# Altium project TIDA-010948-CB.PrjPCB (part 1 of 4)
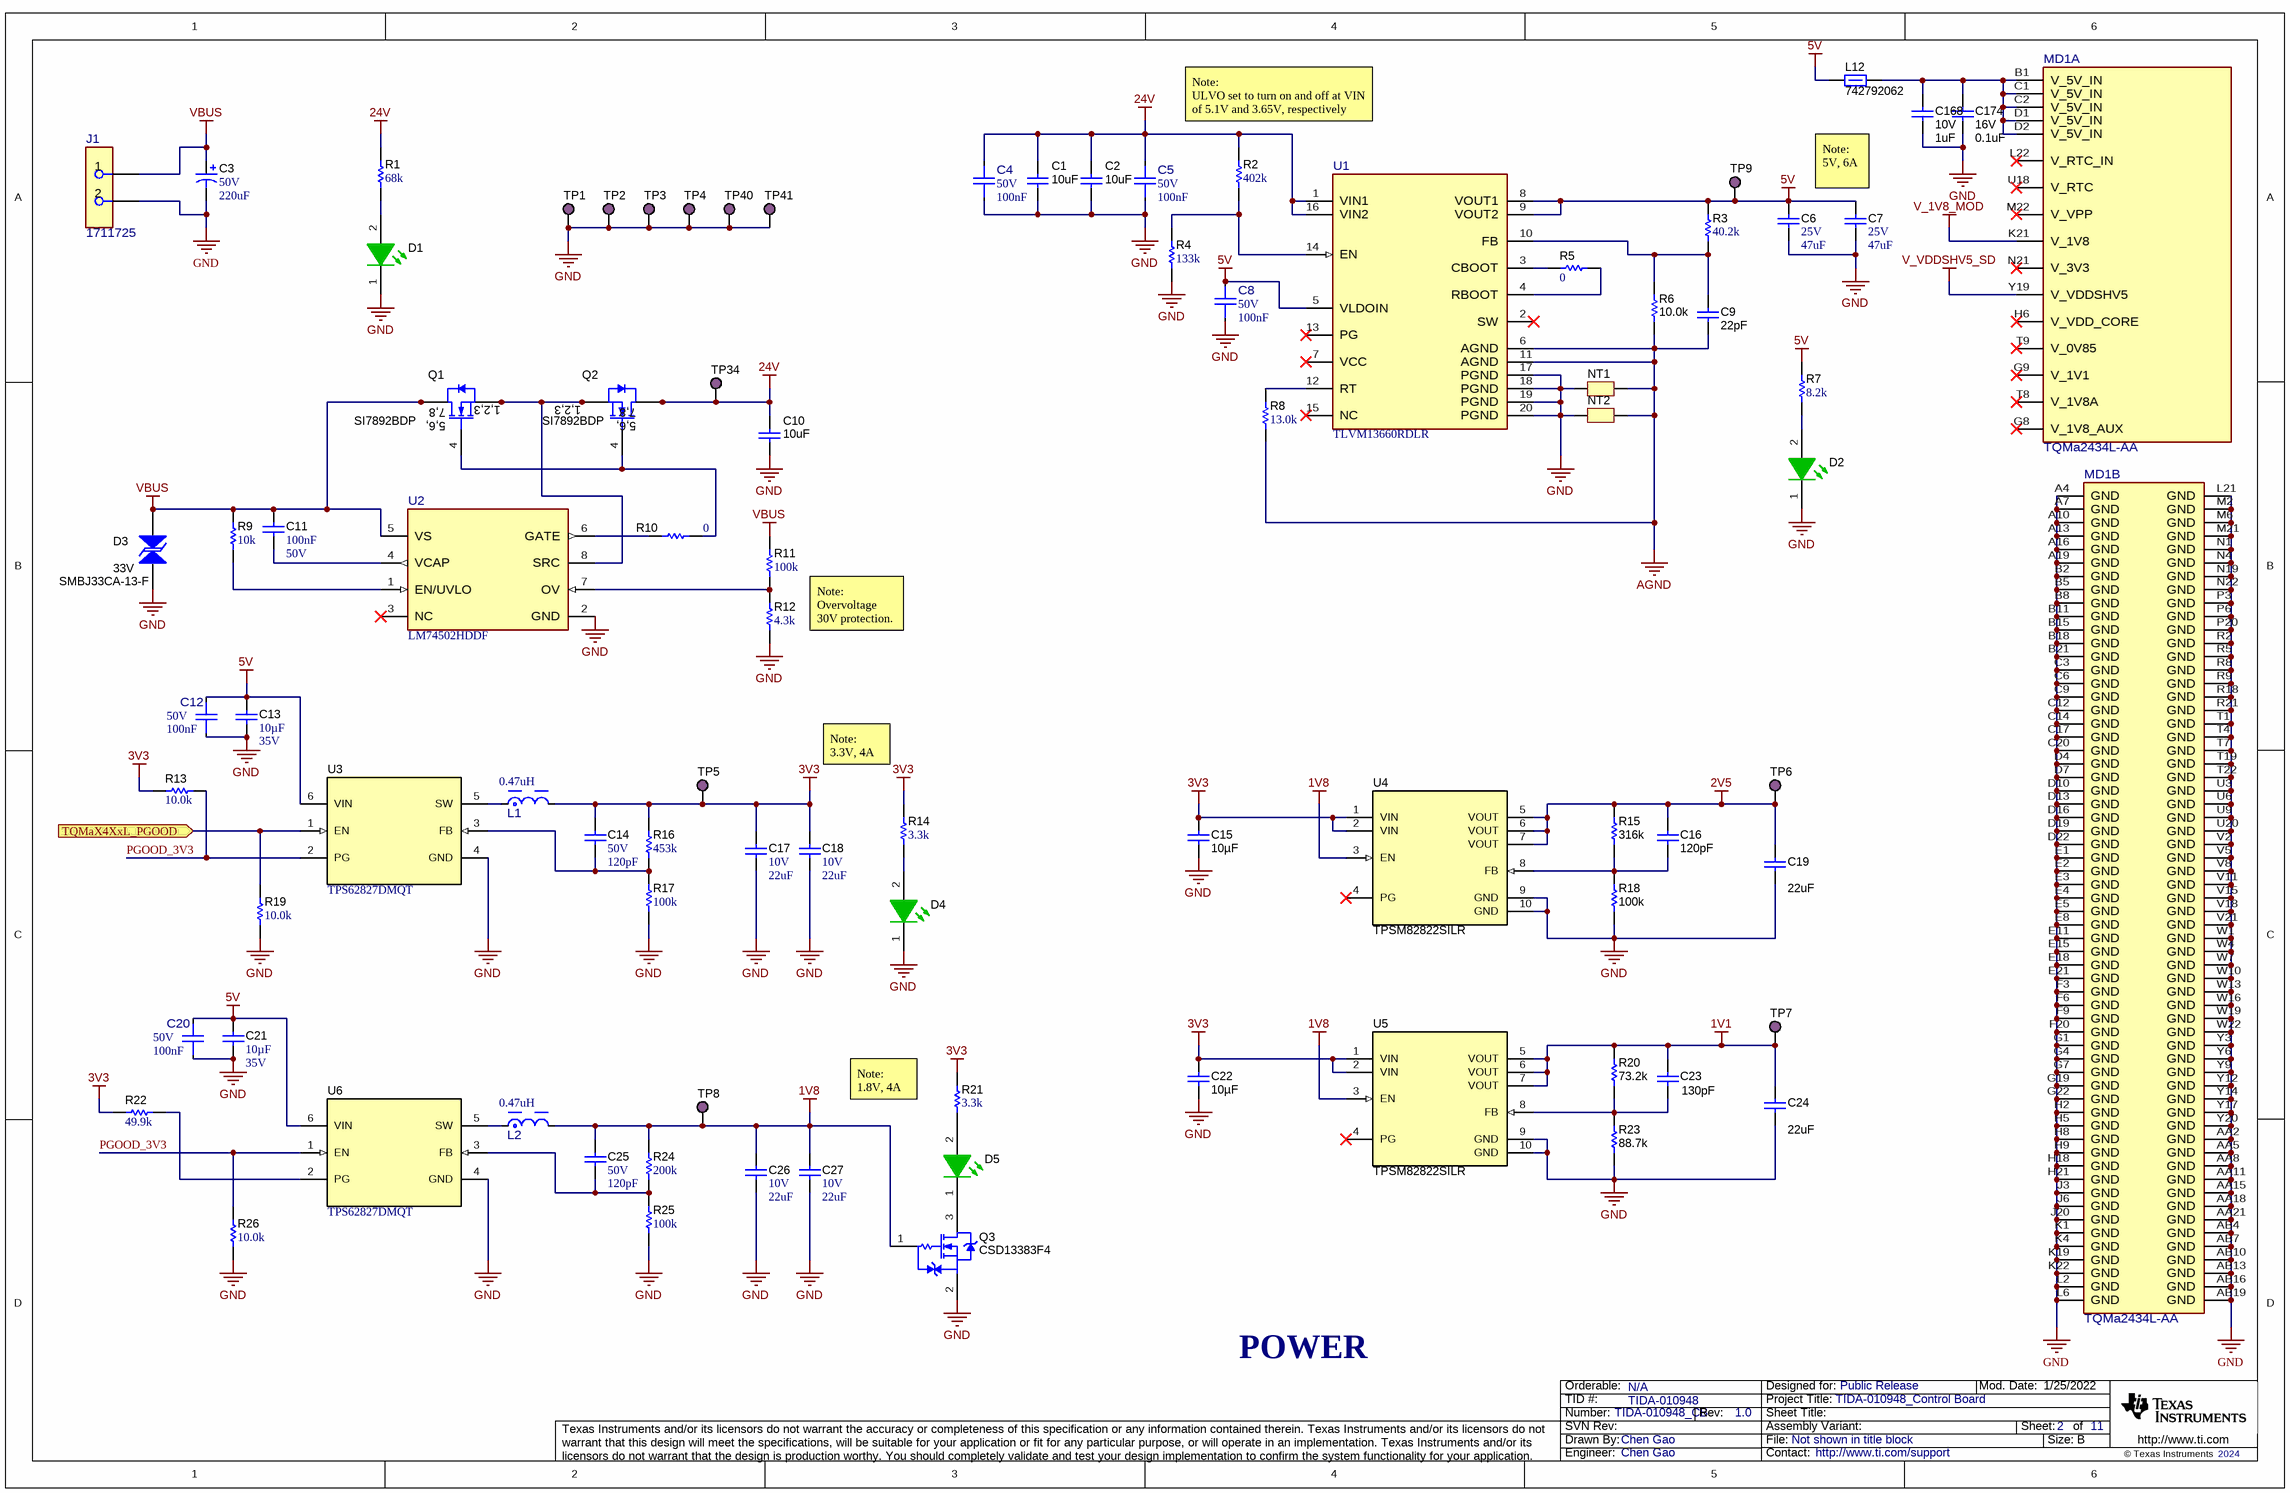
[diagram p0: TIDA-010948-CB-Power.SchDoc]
TID: TIDA-010948; TechSupport: http://www.ti.com/support; SCH_Rev: 1.0; PRJ_Title: TIDA-010948_Control Board; PRJ_Number: TIDA-010948_CB; PRJ_Engineer: Chen Gao; PRJ_Customer: Public Release; PCB_Rev: 1.0; PCB_Layout: TIDA-010948_CB; DrawnBy: Chen Gao; EVM_orderable: N/A; CopyrightYear: 2024
11 sheets, 712 parts. Net scope: flat (ports and power ports of the same name join across sheets).
Board file: TIDA-010948-CB.PcbDoc
Sheets:
  TIDA-010948-CB-BlockDiagram.SchDoc
  TIDA-010948-CB-Power.SchDoc
  TIDA-010948-CB-Bootmode.SchDoc
  TIDA-010948-CB-Debug.SchDoc
  TIDA-010948-CB-SDFM.SchDoc
  TIDA-010948-CB-PRUIO_CLKGEN.SchDoc
  TIDA-010948-CB-PWM.SchDoc
  TIDA-010948-CB-Ethernet1.SchDoc
  TIDA-010948-CB-Ethernet2.SchDoc
  TIDA-010948-CB-Interface.SchDoc
  TIDA-010948-CB-Hardware.SchDoc

## Sheet TIDA-010948-CB-BlockDiagram.SchDoc
size 431 x 279 mm; Date: Not shown in title block; ApprovedBy: Not shown in title block; CheckedBy: Not shown in title block; Author: Not shown in title block; CompanyName: Not shown in title block; Engineer: Not shown in title block; Organization: Not shown in title block; Address1: Not shown in title block; Address2: Not shown in title block; Address3: Not shown in title block; Address4: Not shown in title block; DocumentNumber: 11; Revision: Use project parameter SCH_Rev; SheetNumber: 1; SheetTotal: 11; PageSetup: Record=PageOptions¦CenterHorizontal=True¦CenterVertical=True¦PrintScale=1.00¦XCorrection=1.00¦YCorrection=1.00¦PrintKind=0¦BorderSize=5000000¦LeftOffset=0¦BottomOffset=0¦Orientation=2¦PaperLength=1000¦PaperWidth=1000¦Scale=100¦PaperSource=15¦PrintQuality=600¦MediaType=1¦DitherType=10¦PaperKind=Letter¦PrintScaleMode=1

## Sheet TIDA-010948-CB-Power.SchDoc
size 431 x 279 mm; Date: Not shown in title block; ApprovedBy: Not shown in title block; CheckedBy: Not shown in title block; Author: Not shown in title block; CompanyName: Not shown in title block; Engineer: Not shown in title block; Organization: Not shown in title block; Address1: Not shown in title block; Address2: Not shown in title block; Address3: Not shown in title block; Address4: Not shown in title block; DocumentNumber: 2; Revision: Use project parameter SCH_Rev; SheetNumber: 2; SheetTotal: 11; PageSetup: Record=PageOptions¦CenterHorizontal=True¦CenterVertical=True¦PrintScale=1.00¦XCorrection=1.00¦YCorrection=1.00¦PrintKind=0¦BorderSize=5000000¦LeftOffset=0¦BottomOffset=0¦Orientation=2¦PaperLength=1000¦PaperWidth=1000¦Scale=100¦PaperSource=15¦PrintQuality=600¦MediaType=1¦DitherType=10¦PaperKind=Letter¦PrintScaleMode=1

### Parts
C1  ValueDisplayed: 10uF  [1210_270L]  (hidden comment: GRM32ER71H106KA12L)
C2  ValueDisplayed: 10uF  [1210_270L]  (hidden comment: GRM32ER71H106KA12L)
C3  VDC_V: 50V  ValueDisplayed: 220uF  [SM_RADIAL_G]  (hidden comment: EEE-FK1H221P)
C4  VDC_V: 50V  ValueDisplayed: 100nF  [FP-885012205086_0402-MFG]  (hidden comment: 885012205086)
C5  VDC_V: 50V  ValueDisplayed: 100nF  [FP-885012205086_0402-MFG]  (hidden comment: 885012205086)
C6  VDC_V: 25V  ValueDisplayed: 47uF  [1206_190]  (hidden comment: C3216X5R1E476M160AC)
C7  VDC_V: 25V  ValueDisplayed: 47uF  [1206_190]  (hidden comment: C3216X5R1E476M160AC)
C8  VDC_V: 50V  ValueDisplayed: 100nF  [FP-885012205086_0402-MFG]  (hidden comment: 885012205086)
C9  ValueDisplayed: 22pF  [0402L]  (hidden comment: CGA2B2NP01H220J050BA)
C10  ValueDisplayed: 10uF  [1210_270L]  (hidden comment: GRM32ER71H106KA12L)
C11  Cap_F: 100nF  VDC_V: 50V  [0603]  (hidden comment: GCM188R71H104KA57D)
C12  VDC_V: 50V  ValueDisplayed: 100nF  [FP-885012205086_0402-MFG]  (hidden comment: 885012205086)
C13  ValueDisplayed: 10µF  VDC_V: 35V  [0805_HV1]  (hidden comment: C2012JB1V106K125AC)
C14  VDC_V: 50V  ValueDisplayed: 120pF  [0402L]  (hidden comment: GRM1555C1H121JA01D)
C15  Cap_F: 10µF  [0603]  (hidden comment: GRM188Z71A106MA73D)
C16  ValueDisplayed: 120pF  [0603]  (hidden comment: GRM1885C1H121JA01D)
C17  VDC_V: 10V  ValueDisplayed: 22uF  [0603L]  (hidden comment: GRM187R61A226ME15D)
C18  VDC_V: 10V  ValueDisplayed: 22uF  [0603L]  (hidden comment: GRM187R61A226ME15D)
C19  ValueDisplayed: 22uF  [0805_HV]  (hidden comment: GRM21BR61E226ME44L)
C20  VDC_V: 50V  ValueDisplayed: 100nF  [FP-885012205086_0402-MFG]  (hidden comment: 885012205086)
C21  ValueDisplayed: 10µF  VDC_V: 35V  [0805_HV1]  (hidden comment: C2012JB1V106K125AC)
C22  Cap_F: 10µF  [0603]  (hidden comment: GRM188Z71A106MA73D)
C23  ValueDisplayed: 130pF  [0603]  (hidden comment: GRM1885C1H131JA01D)
C24  ValueDisplayed: 22uF  [0805_HV]  (hidden comment: GRM21BR61E226ME44L)
C25  VDC_V: 50V  ValueDisplayed: 120pF  [0402L]  (hidden comment: GRM1555C1H121JA01D)
C26  VDC_V: 10V  ValueDisplayed: 22uF  [0603L]  (hidden comment: GRM187R61A226ME15D)
C27  VDC_V: 10V  ValueDisplayed: 22uF  [0603L]  (hidden comment: GRM187R61A226ME15D)
C168  VDC_V: 10V  ValueDisplayed: 1uF  [0201]  (hidden comment: GRM033R61A105ME15D)
C174  VDC_V: 16V  ValueDisplayed: 0.1uF  [0201_033]  (hidden comment: GRM033C71C104KE14D)
D1  150040GS73240  [WL-SMCC_0402_Green]  (value not drawn)
D2  150040GS73240  [WL-SMCC_0402_Green]  (value not drawn)
D3  SMBJ33CA-13-F  value 33V  [SMB-Bi]
D4  150040GS73240  [WL-SMCC_0402_Green]  (value not drawn)
D5  150040GS73240  [WL-SMCC_0402_Green]  (value not drawn)
J1  1711725  [FP-1888687_HDR2-MFG]
L1  value 0.47uH  [FP-744383560047HT_1616-MFG]  (hidden comment: 744383560047HT)
L2  value 0.47uH  [FP-744383560047HT_1616-MFG]  (hidden comment: 744383560047HT)
L12  742792062  [0805_HV]
MD1  TQMa2434L-AA  [FP-TQMa2434L-AA_LGA366-MFG]  (parts A,B of 9)
NT1  Net-Tie  [Net-Tie_10milWide_30milLong]  (value not drawn)  (net tie, no BOM)
NT2  Net-Tie  [Net-Tie_10milWide_30milLong]  (value not drawn)  (net tie, no BOM)
Q1  SI7892BDP  [PowerPAK_SO-8]
Q2  SI7892BDP  [PowerPAK_SO-8]
Q3  CSD13383F4  [YJC0003A]
R1  ValueDisplayed: 68k  [0603]  (hidden comment: CRCW060368K0JNEA)
R2  ValueDisplayed: 402k  [0402L]  (hidden comment: CRCW0402402KFKED)
R3  ValueDisplayed: 40.2k  [0402]  (hidden comment: CRCW040240K2FKED)
R4  ValueDisplayed: 133k  [0402L]  (hidden comment: CRCW0402133KFKED)
R5  ValueDisplayed: 0  [0402L]  (hidden comment: CRCW04020000Z0ED)
R6  ValueDisplayed: 10.0k  [0402L]  (hidden comment: CRCW040210K0FKED)
R7  ValueDisplayed: 8.2k  [0402L]  (hidden comment: CRCW04028K20JNED)
R8  ValueDisplayed: 13.0k  [0402L]  (hidden comment: CRCW040213K0FKED)
R9  ValueDisplayed: 10k  [0402]  (hidden comment: CRCW040210K0JNED)
R10  ValueDisplayed: 0  [0402]  (hidden comment: CRCW04020000Z0ED)
R11  ValueDisplayed: 100k  [0402]  (hidden comment: CRCW0402100KFKED)
R12  ValueDisplayed: 4.3k  [0402]  (hidden comment: CRCW04024K30JNED)
R13  ValueDisplayed: 10.0k  [0402L]  (hidden comment: CRCW040210K0FKED)
R14  ValueDisplayed: 3.3k  [0402L]  (hidden comment: CRCW04023K30JNED)
R15  ValueDisplayed: 316k  [0402]  (hidden comment: CRCW0402316KFKED)
R16  ValueDisplayed: 453k  [0402L]  (hidden comment: CRCW0402453KFKED)
R17  ValueDisplayed: 100k  [0402L]  (hidden comment: CRCW0402100KFKED)
R18  ValueDisplayed: 100k  [0402]  (hidden comment: CRCW0402100KFKED)
R19  ValueDisplayed: 10.0k  [0402L]  (hidden comment: CRCW040210K0FKED)
R20  ValueDisplayed: 73.2k  [0402]  (hidden comment: CRCW040273K2FKED)
R21  ValueDisplayed: 3.3k  [0402L]  (hidden comment: CRCW04023K30JNED)
R22  ValueDisplayed: 49.9k  [0402]  (hidden comment: CRCW040249K9FKED)
R23  ValueDisplayed: 88.7k  [0402]  (hidden comment: CRCW040288K7FKED)
R24  ValueDisplayed: 200k  [0402L]  (hidden comment: CRCW0402200KFKED)
R25  ValueDisplayed: 100k  [0402L]  (hidden comment: CRCW0402100KFKED)
R26  ValueDisplayed: 10.0k  [0402L]  (hidden comment: CRCW040210K0FKED)
TP1  5129  [Keystone5129]  (value not drawn)
TP2  5129  [Keystone5129]  (value not drawn)
TP3  5129  [Keystone5129]  (value not drawn)
TP4  5129  [Keystone5129]  (value not drawn)
TP5  5129  [Keystone5129]  (value not drawn)
TP6  5129  [Keystone5129]  (value not drawn)
TP7  5129  [Keystone5129]  (value not drawn)
TP8  5129  [Keystone5129]  (value not drawn)
TP9  5129  [Keystone5129]  (value not drawn)
TP34  5129  [Keystone5129]  (value not drawn)
TP40  5129  [Keystone5129]  (value not drawn)
TP41  5129  [Keystone5129]  (value not drawn)
U1  TLVM13660RDLR  [RDL0020A-MFG]
U2  LM74502HDDF  [DDF0008A-MFG]
U3  TPS62827DMQT  [DMQ0006A]
U4  TPSM82822SILR  [SIL0010D]
U5  TPSM82822SILR  [SIL0010D]
U6  TPS62827DMQT  [DMQ0006A]

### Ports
TQMaX4XxL_PGOOD (in)

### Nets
1V1: C23.1 C24.1 R20.2 TP7.1 U5.5(VOUT) U5.6(VOUT) U5.7(VOUT)
1V8: C25.1 C26.1 C27.1 L2.2 Q3.1(G) R24.2 TP8.1 U4.3(EN) U5.3(EN)
2V5: C16.1 C19.1 R15.2 TP6.1 U4.5(VOUT) U4.6(VOUT) U4.7(VOUT)
3V3: C14.1 C15.1 C17.1 C18.1 C22.1 L1.2 R13.2 R14.2 R16.2 R21.2 R22.2 TP5.1 U4.1(VIN) U4.2(VIN) U5.1(VIN) U5.2(VIN)
5V: C6.1 C7.1 C8.2 C12.2 C13.1 C20.2 C21.1 L12.2 R3.2 R7.2 TP9.1 U1.5(VLDOIN) U1.8(VOUT1) U1.9(VOUT2) U3.6(VIN) U6.6(VIN)
24V: C1.2 C2.2 C4.2 C5.2 C10.2 Q2.5(D) Q2.6(D) Q2.7(D) Q2.8(D) Q2.9(D) R1.2 R2.1 TP34.1 U1.1(VIN1) U1.16(VIN2)
AGND: C9.2 NT1.1 NT2.1 R6.1 R8.1 U1.6(AGND) U1.11(AGND)
GND: C1.1 C2.1 C3.2(-) C4.1 C5.1 C6.2 C7.2 C8.1 C10.1 C12.1 C13.2 C15.2 C17.2 C18.2 C19.2 C20.1 C21.2 C22.2 C24.2 C26.2 C27.2 C168.2 C174.2 D1.1(K) D2.1(K) D3.1 D4.1(K) J1.2 MD1.A4(GND) MD1.A7(GND) MD1.A10(GND) MD1.A13(GND) MD1.A16(GND) MD1.A19(GND) MD1.AA2(GND) MD1.AA5(GND) MD1.AA8(GND) MD1.AA11(GND) MD1.AA15(GND) MD1.AA18(GND) MD1.AA21(GND) MD1.AB4(GND) MD1.AB7(GND) MD1.AB10(GND) MD1.AB13(GND) MD1.AB16(GND) MD1.AB19(GND) MD1.B2(GND) MD1.B5(GND) MD1.B8(GND) MD1.B11(GND) MD1.B15(GND) MD1.B18(GND) MD1.B21(GND) MD1.C3(GND) MD1.C6(GND) MD1.C9(GND) MD1.C12(GND) MD1.C14(GND) MD1.C17(GND) MD1.C20(GND) MD1.D4(GND) MD1.D7(GND) MD1.D10(GND) MD1.D13(GND) MD1.D16(GND) MD1.D19(GND) MD1.D22(GND) MD1.E1(GND) MD1.E2(GND) MD1.E3(GND) MD1.E4(GND) MD1.E5(GND) MD1.E8(GND) MD1.E11(GND) MD1.E15(GND) MD1.E18(GND) MD1.E21(GND) MD1.F3(GND) MD1.F6(GND) MD1.F9(GND) MD1.F20(GND) MD1.G1(GND) MD1.G4(GND) MD1.G7(GND) MD1.G19(GND) MD1.G22(GND) MD1.H2(GND) MD1.H5(GND) MD1.H8(GND) MD1.H9(GND) MD1.H18(GND) MD1.H21(GND) MD1.J3(GND) MD1.J6(GND) MD1.J20(GND) MD1.K1(GND) MD1.K4(GND) MD1.K19(GND) MD1.K22(GND) MD1.L2(GND) MD1.L6(GND) MD1.L21(GND) MD1.M2(GND) MD1.M6(GND) MD1.M21(GND) MD1.N1(GND) MD1.N4(GND) MD1.N19(GND) MD1.N22(GND) MD1.P3(GND) MD1.P6(GND) MD1.P20(GND) MD1.R2(GND) MD1.R5(GND) MD1.R8(GND) MD1.R9(GND) MD1.R18(GND) MD1.R21(GND) MD1.T1(GND) MD1.T4(GND) MD1.T7(GND) MD1.T19(GND) MD1.T22(GND) MD1.U3(GND) MD1.U6(GND) MD1.U9(GND) MD1.U20(GND) MD1.V2(GND) MD1.V5(GND) MD1.V8(GND) MD1.V11(GND) MD1.V15(GND) MD1.V18(GND) MD1.V21(GND) MD1.W1(GND) MD1.W4(GND) MD1.W7(GND) MD1.W10(GND) MD1.W13(GND) MD1.W16(GND) MD1.W19(GND) MD1.W22(GND) MD1.Y3(GND) MD1.Y6(GND) MD1.Y9(GND) MD1.Y12(GND) MD1.Y14(GND) MD1.Y17(GND) MD1.Y20(GND) NT1.2 NT2.2 Q3.2(S) R4.2 R12.1 R17.1 R18.1 R19.1 R23.1 R25.1 R26.1 TP1.1 TP2.1 TP3.1 TP4.1 TP40.1 TP41.1 U1.17(PGND) U1.18(PGND) U1.19(PGND) U1.20(PGND) U2.2(GND) U3.4(GND) U4.9(GND) U4.10(GND) U5.9(GND) U5.10(GND) U6.4(GND)
V_1V8_MOD: MD1.K21(V_1V8)
V_VDDSHV5_SD: MD1.Y19(V_VDDSHV5)
VBUS: C3.1(+) C11.1 D3.2 J1.1 Q1.5(D) Q1.6(D) Q1.7(D) Q1.8(D) Q1.9(D) R9.2 R11.2 U2.5(VS)
PGOOD_3V3: R13.1 R26.2 U3.2(PG) U6.1(EN)
TQMaX4XxL_PGOOD: R19.2 U3.1(EN) ; port TQMaX4XxL_PGOOD
NetC9_1: C9.1 R3.1 R6.2 U1.10(FB)
NetC11_2: C11.2 U2.4(VCAP)
NetC14_2: C14.2 R16.1 R17.2 U3.3(FB)
NetC16_2: C16.2 R15.1 R18.2 U4.8(FB)
NetC23_2: C23.2 R20.1 R23.2 U5.8(FB)
NetC25_2: C25.2 R24.1 R25.2 U6.3(FB)
NetC168_1: C168.1 C174.1 L12.1 MD1.B1(V_5V_IN) MD1.C1(V_5V_IN) MD1.C2(V_5V_IN) MD1.D1(V_5V_IN) MD1.D2(V_5V_IN)
NetD1_2: D1.2(A) R1.1
NetD2_2: D2.2(A) R7.1
NetD4_2: D4.2(A) R14.1
NetD5_1: D5.1(K) Q3.3(D)
NetD5_2: D5.2(A) R21.1
NetL1_1: L1.1 U3.5(SW)
NetL2_1: L2.1 U6.5(SW)
NetQ1_1: Q1.1(S) Q1.2(S) Q1.3(S) Q2.1(S) Q2.2(S) Q2.3(S) U2.8(SRC)
NetQ1_4: Q1.4(G) Q2.4(G) R10.1
NetR2_2: R2.2 R4.1 U1.14(EN)
NetR5_1: R5.1 U1.3(CBOOT)
NetR5_2: R5.2 U1.4(RBOOT)
NetR8_2: R8.2 U1.12(RT)
NetR9_1: R9.1 U2.1(EN/UVLO)
NetR10_2: R10.2 U2.6(GATE)
NetR11_1: R11.1 R12.2 U2.7(OV)
NetR22_1: R22.1 U6.2(PG)

Not connected (* = marked no-connect by the designer): MD1 G8(V_1V8_AUX)* G9(V_1V1)* H6(V_VDD_CORE)* L22(V_RTC_IN)* M22(V_VPP)* N21(V_3V3)* T8(V_1V8A)* T9(V_0V85)* U18(V_RTC)*; U1 2(SW)* 7(VCC)* 13(PG)* 15(NC)*; U2 3(NC)*; U4 4(PG)*; U5 4(PG)*

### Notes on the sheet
- Note:
  ULVO set to turn on and off at VIN of 5.1V and 3.65V, respectively
- Note:
  5V, 6A
- Note:
  Overvoltage 30V protection.
- Note:
  3.3V, 4A
- (near R21) Note:
  1.8V, 4A
- POWER

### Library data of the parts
C1 C2 C10 = CMP-0009226-3: CAP, CERM, 10 uF, 50 V, +/- 10%, X7R, 1210; Manufacturer: MuRata; TaMin_C: -55°C; Polarized: N; SizeAreaWB_mm2: 14.7; Value1: Unknown; U/M: EA; Value: 10uF; TaMax_C: 125°C; SizeZ_mm: 2.7; SizeX_mm: 3.2; SizeY_mm: 2.5; Cap_Case: 1210; Value2: 50V; SizeArea_mm2: 8; Cap_F: 10µF; AEC Category: Q200
C3 = CMP-0011181-2: CAP, AL, 220 uF, 50 V, +/- 20%, 0.18 ohm, AEC-Q200 Grade 2, SMD; Manufacturer: Panasonic; TaMin_C: -55°C; ESR_ohm: 0.18; Polarized: Y; SizeAreaWB_mm2: 172.2; U/M: EA; Value: 220uF; TaMax_C: 105°C; SizeZ_mm: 10.2; SizeX_mm: 12; SizeY_mm: 10.3; Cap_Case: G; SizeArea_mm2: 123.6; CompType: Capacitor; Cap_F: 220µF; IRMS_A: 670mA; AEC Grade: 2; AEC Category: Q200
C4 C5 C8 C12 C20 = CMP-0096737-1: 100 nF ±10% 50V Ceramic Capacitor X7R 0402 (1005 Metric); Manufacturer: Wurth; SizeZ_mm: 0.7mm; TempCo: 15%; AEC Qualified: No; Value: 100nF
C6 C7 = CMP-0008656-2: CAP, CERM, 47 uF, 25 V, +/- 20%, X5R, 1206_190; Manufacturer: TDK; TaMin_C: -55°C; Polarized: N; SizeAreaWB_mm2: 10.92; Value1: Unknown; U/M: EA; Value: 47uF; TaMax_C: 85°C; SizeZ_mm: 1.9; SizeX_mm: 3.2; SizeY_mm: 1.6; Cap_Case: 1206; SizeArea_mm2: 5.12; Cap_F: 47µF; AEC Category: Q200
C9 = CMP-0006311-2: CAP, CERM, 22 pF, 50 V, +/- 5%, C0G/NP0, AEC-Q200 Grade 1, 0402; Manufacturer: TDK; TaMin_C: -55°C; Polarized: N; SizeAreaWB_mm2: 3; Value1: Unknown; U/M: EA; Value: 22pF; TaMax_C: 125°C; SizeZ_mm: 0.6; SizeX_mm: 1; SizeY_mm: 0.5; Cap_Case: 0402; Value2: 50V; AEC Qualified: Y; AEC Category: Q200
C11 = CMP-0007144-4: CAP, CERM, 0.1 uF, 50 V, +/- 10%, X7R, 0603; Manufacturer: MuRata; TaMin_C: -55°C; ESR_ohm: 20m; Polarized: N; SizeAreaWB_mm2: 4.68; Value1: 0.02 ohm; U/M: EA; Value: 0.1uF; TaMax_C: 125°C; SizeZ_mm: 1; SizeX_mm: 1.6; SizeY_mm: 0.8; SizeArea_mm2: 1.28; IRMS_A: 1.84A; AEC Category: Q200
C13 C21 = CMP-0085894-1: CAP, CERM, 10 µF, 35 V,+/- 10%, JB, 0805; Manufacturer: TDK; SizeY_mm: 1.25; AEC Category: Q200; SizeArea_mm2: 2.5; Cap_Case: 0805; AEC Qualified: N; SizeX_mm: 2; Value: 10uF; U/M: EA; SizeZ_mm: 1.45; SizeAreaWB_mm2: 6.75; TaMax_C: 85°C; TaMin_C: -25°C
C14 C25 = CMP-0006417-2: CAP, CERM, 120 pF, 50 V, +/- 5%, C0G/NP0, 0402; Manufacturer: MuRata; TaMin_C: -55°C; Polarized: N; SizeAreaWB_mm2: 3; Value1: Unknown; U/M: EA; Value: 120pF; TaMax_C: 125°C; SizeZ_mm: 0.6; SizeX_mm: 1; SizeY_mm: 0.5; Cap_Case: 0402; AEC Category: Q200
C15 C22 = CMP-0007497-5: CAP, CERM, 10 uF, 10 V, +/- 20%, X7R, 0603; Manufacturer: MuRata; TaMin_C: -55°C; Polarized: N; SizeAreaWB_mm2: 4.68; Value1: Unknown; U/M: EA; Value: 10uF; TaMax_C: 125°C; SizeZ_mm: 1; SizeX_mm: 1.6; SizeY_mm: 0.8; Value2: 10V; SizeArea_mm2: 1.28; AEC Category: Q200
C16 = CMP-0007179-4: CAP, CERM, 120 pF, 50 V, +/- 5%, C0G/NP0, 0603; Manufacturer: MuRata; TaMin_C: -55°C; Polarized: N; SizeAreaWB_mm2: 4.68; Value1: Unknown; U/M: EA; Value: 120pF; TaMax_C: 125°C; SizeZ_mm: 1; SizeX_mm: 1.6; SizeY_mm: 0.8; Value2: 50V; SizeArea_mm2: 1.28; AEC Category: Q200
C17 C18 C26 C27 = CMP-0007158-5: CAP, CERM, 22 uF, 10 V, +/- 20%, X5R, 0603; Manufacturer: MuRata; TaMin_C: -55°C; Polarized: N; SizeAreaWB_mm2: 4.68; Value1: Unknown; U/M: EA; Value: 22uF; TaMax_C: 85°C; SizeZ_mm: 1; SizeX_mm: 1.6; SizeY_mm: 0.8; Cap_Case: 0603; SizeArea_mm2: 1.28; Cap_F: 22µF; AEC Category: Q200
C19 C24 = CMP-0008305-2: CAP, CERM, 22 uF, 25 V, +/- 20%, X5R, 0805; Manufacturer: MuRata; TaMin_C: -55°C; Polarized: N; SizeAreaWB_mm2: 6.75; Value1: Unknown; U/M: EA; Value: 22uF; TaMax_C: 85°C; SizeZ_mm: 1.45; SizeX_mm: 2; SizeY_mm: 1.25; Cap_Case: 0805; Value2: 25V; SizeArea_mm2: 2.5; Cap_F: 22µF; AEC Category: Q200
C23 = CMP-0007182-4: CAP, CERM, 130 pF, 50 V, +/- 5%, C0G/NP0, 0603; Manufacturer: MuRata; TaMin_C: -55°C; Polarized: N; SizeAreaWB_mm2: 4.68; Value1: Unknown; U/M: EA; Value: 130pF; TaMax_C: 125°C; SizeZ_mm: 1; SizeX_mm: 1.6; SizeY_mm: 0.8; Value2: 50V; SizeArea_mm2: 1.28; AEC Category: Q200
C168 = CMP-0064909-1: CAP, CERM, 1 uF, 10 V,+/- 20%, X5R, 0201; Manufacturer: MuRata; TaMin_C: -55°C; Polarized: N; SizeAreaWB_mm2: 2.08; Value1: Unknown; U/M: EA; Value: 1uF; TaMax_C: 85°C; SizeZ_mm: 0.26; SizeX_mm: 0.6; SizeY_mm: 0.3; SizeArea_mm2: 0.18; Cap_F: 1µF; AEC Category: Q200
C174 = CMP-0009670-3: CAP, CERM, 0.1 uF, 16 V, +/- 10%, X5R, 0201; Manufacturer: MuRata; TaMin_C: -55°C; Polarized: N; SizeAreaWB_mm2: 2.08; Value1: Unknown; U/M: EA; Value: 0.1uF; TaMax_C: 125°C; SizeZ_mm: 0.33; SizeX_mm: 0.6; SizeY_mm: 0.3; Cap_Case: 0201; SizeArea_mm2: 0.18; Cap_F: 100nF; AEC Category: Q200
D1 D2 D4 D5 = CMP-0081765-2: LED, Green, SMD; Manufacturer: Wurth Elektronik; Vr_V: 5V; Io_A: 20mA; Tjmax_C: 95°C; Ir_A: 10µA; Power_TotalModule: 99mW; Value2: 3.2V; SizeArea_mm2: 0.5; SizeX_mm: 1; Value1: 0.099W; Angle: 120; Type: InGaN; SizeAreaWB_mm2: 3
D3 = CMP-0005564-3: Diode, TVS, Bi, 33 V, SMB; Manufacturer: Diodes Inc.; SizeX_mm: 5.6; Ppk: 600W; SizeAreaWB_mm2: 44.156; SizeZ_mm: 2.6; SizeArea_mm2: 21.336; SizeY_mm: 3.81; AEC Category: Q101
J1 = CMP-0087130-1: Manufacturer: Phoenix Contact; Voltage_V: 400V; Current_A: 15A; Row_Count: 1; ContactFinish: Tin
L1 L2 = CMP-0096734-1: 470 nH Shielded - Inductor 8.5 A 8.1mOhm Max 1616 (4040 Metric) -; Manufacturer: Wurth; Shrouded: true; Test Frequency: 100kHz; TaMax_C: +110°C; Tolerance_%: 30%; Self Resonant Frequency: 83MHz; AEC Qualified: No; Irms: 8.5A; Material: Magnetic Iron Alloy; DCR_ohm: 8.1m; Ind_H: 470nH; SizeZ_mm: 2.1mm; Isat: 10A; TaMin_C: -55°C; AEC Grade: NA
L12 = CMP-0003092-1: Ferrite Bead, 80 ohm @ 100 MHz, 0.5 A, 0805; Manufacturer: Wurth Elektronik; Ztyp@1GHz_Ohm: 146.576; ZTyp@100MHz_Ohm: 80; SizeAreaWB_mm2: 6.75; DCR_ohm: 0.2; Value1: 0.2 ohm; Value: 80 ohm; Imax_A: 500mA; SizeZ_mm: 1.45; SizeX_mm: 2; SizeY_mm: 1.25; Value2: 0.5A; SizeArea_mm2: 2.5
MD1 = CMP-0120622-1: Embedded Cortex®- R5F module based on TI AM243x for headless Applications with Real - time demand; Manufacturer: TQ-Group; SizeZ_mm: 6.34mm; AEC Qualified: No; Core Architecture: ARM Cortex-R5F; Frequency_Fixed: 800MHz; Interface: I2C,SPI,UART,CAN,USB,Ethernet,PCIe; Max Supply Voltage: 5.25V; Memory Size: 64MBytes; Memory Type: FLASH,NOR; Min Supply Voltage: 4.75V; Number Of A/D Converters: 1; Number Of Cores: 2; Number Of Ethernet Channels: 6; Number Of Spi Channels: 8; Number Of Uart Channels: 9; Ram Size: 1GBytes
NT1 NT2 = CMP-0078142-4: Single point connection between nets.
Q1 Q2 = CMP-0000665-1: MOSFET, N-CH, 30 V, 15 A, PowerPAK SO-8; Alternate Manufacturer: None; Manufacturer: Vishay-Siliconix; SizeZ_mm: 1.12; ChType: N; Value2: 27 nC; Value1: 0.005; VdsMax_V: 30V; SizeX_mm: 5.99; SizeAreaWB_mm2: 55.131; SizeY_mm: 4.9; Vgs_V: 20V; QgTyp_nC: 27; Value: 30V; Rdson45_ohm: 5.7m; SizeArea_mm2: 29.351; AEC Category: Q101; IdsMax_A: 15A; U/M: EA
Q3 = CMP-0000198-1: MOSFET, N-CH, 12 V, 2.9 A, YJC0003A (PICOSTAR-3); Alternate Manufacturer: None; Manufacturer: Texas Instruments; SizeZ_mm: 0.35; ChType: N; Value2: 2 nC; Value1: 0.04; VdsMax_V: 12V; SizeX_mm: 1.035; SizeY_mm: 0.635; Vgs_V: 10V; Value: 12V; Rdson45_ohm: 0.044; SizeArea_mm2: 0.657225; AEC Category: Q101; IdsMax_A: 2.9A; SizeAreaWB_mm2: 3.327225; U/M: EA; QgTyp_nC: 2
R1 = CMP-0025842-4: RES, 68 k, 5%, 0.1 W, AEC-Q200 Grade 0, 0603; Manufacturer: Vishay-Dale; Power_W: 100mW; TempCo: 200 ppm/C; Value_Code: 68k0; Value: 68k; EIA_Code: E24; SizeX_mm: 1.6; SizeY_mm: 0.8; SizeZ_mm: 1; Value2: 0.1W; SizeArea_mm2: 1.28; AEC Qualified: Y; VDC_V: 75V; AEC Category: Q200; AEC Grade: 0
R2 = CMP-0026365-1: RES, 402 k, 1%, 0.063 W, 0402; Manufacturer: Vishay-Dale; Power_W: 63mW; TempCo: 100 ppm/C; U/M: EA; Value: 402k; EIA_Code: E96; SizeX_mm: 1; SizeY_mm: 0.5; SizeZ_mm: 0.6; Value2: 0.063W; VDC_V: 50V; AEC Category: Q200
R3 = CMP-0026367-2: RES, 40.2 k, 1%, 0.063 W, AEC-Q200 Grade 0, 0402; Manufacturer: Vishay-Dale; Power_W: 63mW; TempCo: 100 ppm/C; Value_Code: 40k2; Value: 40.2k; EIA_Code: E96; SizeX_mm: 1; SizeY_mm: 0.5; SizeZ_mm: 0.6; Value2: 0.063W; AEC Qualified: Y; VDC_V: 50V; AEC Category: Q200; AEC Grade: 0
R4 = CMP-0025999-1: RES, 133 k, 1%, 0.063 W, 0402; Manufacturer: Vishay-Dale; Power_W: 63mW; TempCo: 100 ppm/C; U/M: EA; Value: 133k; EIA_Code: E96; SizeX_mm: 1; SizeY_mm: 0.5; SizeZ_mm: 0.6; Value2: 0.063W; VDC_V: 50V; AEC Category: Q200
R5 R10 = CMP-0026822-3: RES, 0, 5%, 0.063 W, AEC-Q200 Grade 0, 0402; Manufacturer: Vishay-Dale; Power_W: 63mW; TempCo: 200 ppm/C; Value_Code: 0000; Value: 0; EIA_Code: E24; SizeX_mm: 1; SizeY_mm: 0.5; SizeZ_mm: 0.6; Value2: 0.063W; AEC Qualified: Y; VDC_V: 50V; AEC Category: Q200
R6 R13 R19 R26 = CMP-0025958-3: RES, 10.0 k, 1%, 0.063 W, AEC-Q200 Grade 0, 0402; Manufacturer: Vishay-Dale; Power_W: 63mW; TempCo: 100 ppm/C; Value_Code: 10k0; Value: 10.0k; EIA_Code: E96; Res_ohm: 10k; SizeX_mm: 1; SizeY_mm: 0.5; SizeZ_mm: 0.6; Value2: 0.063W; AEC Qualified: Y; VDC_V: 50V; AEC Category: Q200; AEC Grade: 0
R7 = CMP-0026982-5: RES, 8.2 k, 5%, 0.063 W, AEC-Q200 Grade 0, 0402; Manufacturer: Vishay-Dale; Power_W: 63mW; TempCo: 200 ppm/C; Value_Code: 8k20; Value: 8.2k; EIA_Code: E24; SizeX_mm: 1; SizeY_mm: 0.5; SizeZ_mm: 0.6; Value2: 0.063W; AEC Qualified: Y; VDC_V: 50V; AEC Category: Q200; AEC Grade: 0
R8 = CMP-0026003-3: RES, 13.0 k, 1%, 0.063 W, AEC-Q200 Grade 0, 0402; Manufacturer: Vishay-Dale; Power_W: 63mW; TempCo: 100 ppm/C; Value_Code: 13k0; Value: 13.0k; EIA_Code: E96; Res_ohm: 13k; SizeX_mm: 1; SizeY_mm: 0.5; SizeZ_mm: 0.6; Value2: 0.063W; AEC Qualified: Y; VDC_V: 50V; AEC Category: Q200; AEC Grade: 0
R9 = CMP-0026825-5: RES, 10 k, 5%, 0.063 W, AEC-Q200 Grade 0, 0402; Manufacturer: Vishay-Dale; Power_W: 63mW; TempCo: 200 ppm/C; Value_Code: 10k0; Value: 10k; EIA_Code: E24; SizeX_mm: 1; SizeY_mm: 0.5; SizeZ_mm: 0.6; Value2: 0.063W; AEC Qualified: Y; VDC_V: 50V; AEC Category: Q200; AEC Grade: 0
R11 R17 R18 R25 = CMP-0025950-3: RES, 100 k, 1%, 0.063 W, AEC-Q200 Grade 0, 0402; Manufacturer: Vishay-Dale; Power_W: 63mW; TempCo: 100 ppm/C; Value: 100k; EIA_Code: E96; SizeX_mm: 1; SizeY_mm: 0.5; SizeZ_mm: 0.6; Value2: 0.063W; AEC Qualified: Y; VDC_V: 50V; AEC Category: Q200; AEC Grade: 0
R12 = CMP-0026937-5: RES, 4.3 k, 5%, 0.063 W, AEC-Q200 Grade 0, 0402; Manufacturer: Vishay-Dale; Power_W: 63mW; TempCo: 200 ppm/C; Value_Code: 4k30; Value: 4.3k; EIA_Code: E24; SizeX_mm: 1; SizeY_mm: 0.5; SizeZ_mm: 0.6; Value2: 0.063W; AEC Qualified: Y; VDC_V: 50V; AEC Category: Q200; AEC Grade: 0
R14 R21 = CMP-0026918-5: RES, 3.3 k, 5%, 0.063 W, AEC-Q200 Grade 0, 0402; Manufacturer: Vishay-Dale; Power_W: 63mW; TempCo: 200 ppm/C; Value_Code: 3k30; Value: 3.3k; EIA_Code: E24; SizeX_mm: 1; SizeY_mm: 0.5; SizeZ_mm: 0.6; Value2: 0.063W; AEC Qualified: Y; VDC_V: 50V; AEC Category: Q200; AEC Grade: 0
R15 = CMP-0026288-2: RES, 316 k, 1%, 0.063 W, AEC-Q200 Grade 0, 0402; Manufacturer: Vishay-Dale; Power_W: 63mW; TempCo: 100 ppm/C; Value: 316k; EIA_Code: E96; SizeX_mm: 1; SizeY_mm: 0.5; SizeZ_mm: 0.6; Value2: 0.063W; AEC Qualified: Y; VDC_V: 50V; AEC Category: Q200; AEC Grade: 0
R16 = CMP-0026385-2: RES, 453 k, 1%, 0.063 W, AEC-Q200 Grade 0, 0402; Manufacturer: Vishay-Dale; Power_W: 63mW; TempCo: 100 ppm/C; Value: 453k; EIA_Code: E96; SizeX_mm: 1; SizeY_mm: 0.5; SizeZ_mm: 0.6; Value2: 0.063W; AEC Qualified: Y; VDC_V: 50V; AEC Category: Q200; AEC Grade: 0
R20 = CMP-0026539-2: RES, 73.2 k, 1%, 0.063 W, AEC-Q200 Grade 0, 0402; Manufacturer: Vishay-Dale; Power_W: 63mW; TempCo: 100 ppm/C; Value_Code: 73k2; Value: 73.2k; EIA_Code: E96; SizeX_mm: 1; SizeY_mm: 0.5; SizeZ_mm: 0.6; Value2: 0.063W; AEC Qualified: Y; VDC_V: 50V; AEC Category: Q200; AEC Grade: 0
R22 = CMP-0026403-2: RES, 49.9 k, 1%, 0.063 W, AEC-Q200 Grade 0, 0402; Manufacturer: Vishay-Dale; Power_W: 63mW; TempCo: 100 ppm/C; Value_Code: 49k9; Value: 49.9k; EIA_Code: E96; SizeX_mm: 1; SizeY_mm: 0.5; SizeZ_mm: 0.6; Value2: 0.063W; AEC Qualified: Y; VDC_V: 50V; AEC Category: Q200; AEC Grade: 0
R23 = CMP-0026586-2: RES, 88.7 k, 1%, 0.063 W, AEC-Q200 Grade 0, 0402; Manufacturer: Vishay-Dale; Power_W: 63mW; TempCo: 100 ppm/C; Value_Code: 88k7; Value: 88.7k; EIA_Code: E96; SizeX_mm: 1; SizeY_mm: 0.5; SizeZ_mm: 0.6; Value2: 0.063W; AEC Qualified: Y; VDC_V: 50V; AEC Category: Q200; AEC Grade: 0
R24 = CMP-0026158-2: RES, 200 k, 1%, 0.063 W, AEC-Q200 Grade 0, 0402; Manufacturer: Vishay-Dale; Power_W: 63mW; TempCo: 100 ppm/C; Value: 200k; EIA_Code: E96; SizeX_mm: 1; SizeY_mm: 0.5; SizeZ_mm: 0.6; Value2: 0.063W; AEC Qualified: Y; VDC_V: 50V; AEC Category: Q200; AEC Grade: 0
TP1-TP9 TP34 TP40 TP41 = CMP-0055160-1: Test Point, Multipurpose, Purple, TH; Manufacturer: Keystone; CNHeader: FALSE; ContactFinish: Silver; CT: TRUE
U1 = CMP-0093355-3: Cruzline-6A Power Module 36Vin 1 Ajustable-Output 1-6V B3QFN20 200-2200kHz SW Freq; Manufacturer: Texas Instruments; Output Type: AdjustableProgrammable; Switching Topology: Buck; AEC Category: Q200; CompType: IC; TJmax_C: +125°C; SizeZ_mm: 4.1mm; TaMax_C: +105°C; TaMin_C: -40°C; Number Of Outputs: 1; AEC Qualified: No; Max Supply Voltage: 36V; Min Supply Voltage: 3V
U2 = CMP-0095578-1: Low IQ High Side Switch Controller With Reverse Polarity and Overvoltage Protection; Manufacturer: Texas Instruments; TJmax_C: +150°C; AEC Qualified: No; SizeZ_mm: 1.1mm; Nominal Supply Current: 45uA; Min Supply Voltage: 4V; Number Of Outputs: 1; Standoff Height: 0mm; Max Supply Voltage: 60V; TaMax_C: +125°C; TaMin_C: -40°C
U3 U6 = CMP-0083727-1: 4-A Step-Down Converter with 1% Output Accuracy, DMQ0006A (VSON-HR-6); Alternate PartNumber: TPS62827DMQR; Alternate Manufacturer: Texas Instruments; SizeAreaWB_mm2: 6.25; SizeZ_mm: 1; SizeX_mm: 1.5; SizeArea_mm2: 2.25; CompType: IC; AEC Qualified: N; AEC Category: Q200
U4 U5 = CMP-0860376-1: 1A and 2-A High Efficiency Step-Down Converter MicroSiPTM with Integrated Inductor, SIL0010D (uSIP-10); Manufacturer: Texas Instruments; Alternate PartNumber: TPSM82822SILT; SizeY_mm: 2.5; SizeZ_mm: 1.35; CompType: IC; SizeAreaWB_mm2: 10.5; SizeX_mm: 2; SizeArea_mm2: 5; AEC Category: Q200; AEC Qualified: N

## Sheet TIDA-010948-CB-Bootmode.SchDoc
size 431 x 279 mm; Date: Not shown in title block; ApprovedBy: Not shown in title block; CheckedBy: Not shown in title block; Author: Not shown in title block; CompanyName: Not shown in title block; Engineer: Not shown in title block; Organization: Not shown in title block; Address1: Not shown in title block; Address2: Not shown in title block; Address3: Not shown in title block; Address4: Not shown in title block; DocumentNumber: 3; Revision: Use project parameter SCH_Rev; SheetNumber: 3; SheetTotal: 11; PageSetup: Record=PageOptions¦CenterHorizontal=True¦CenterVertical=True¦PrintScale=1.00¦XCorrection=1.00¦YCorrection=1.00¦PrintKind=0¦BorderSize=5000000¦LeftOffset=0¦BottomOffset=0¦Orientation=2¦PaperLength=1000¦PaperWidth=1000¦Scale=100¦PaperSource=15¦PrintQuality=600¦MediaType=1¦DitherType=10¦PaperKind=Letter¦PrintScaleMode=1
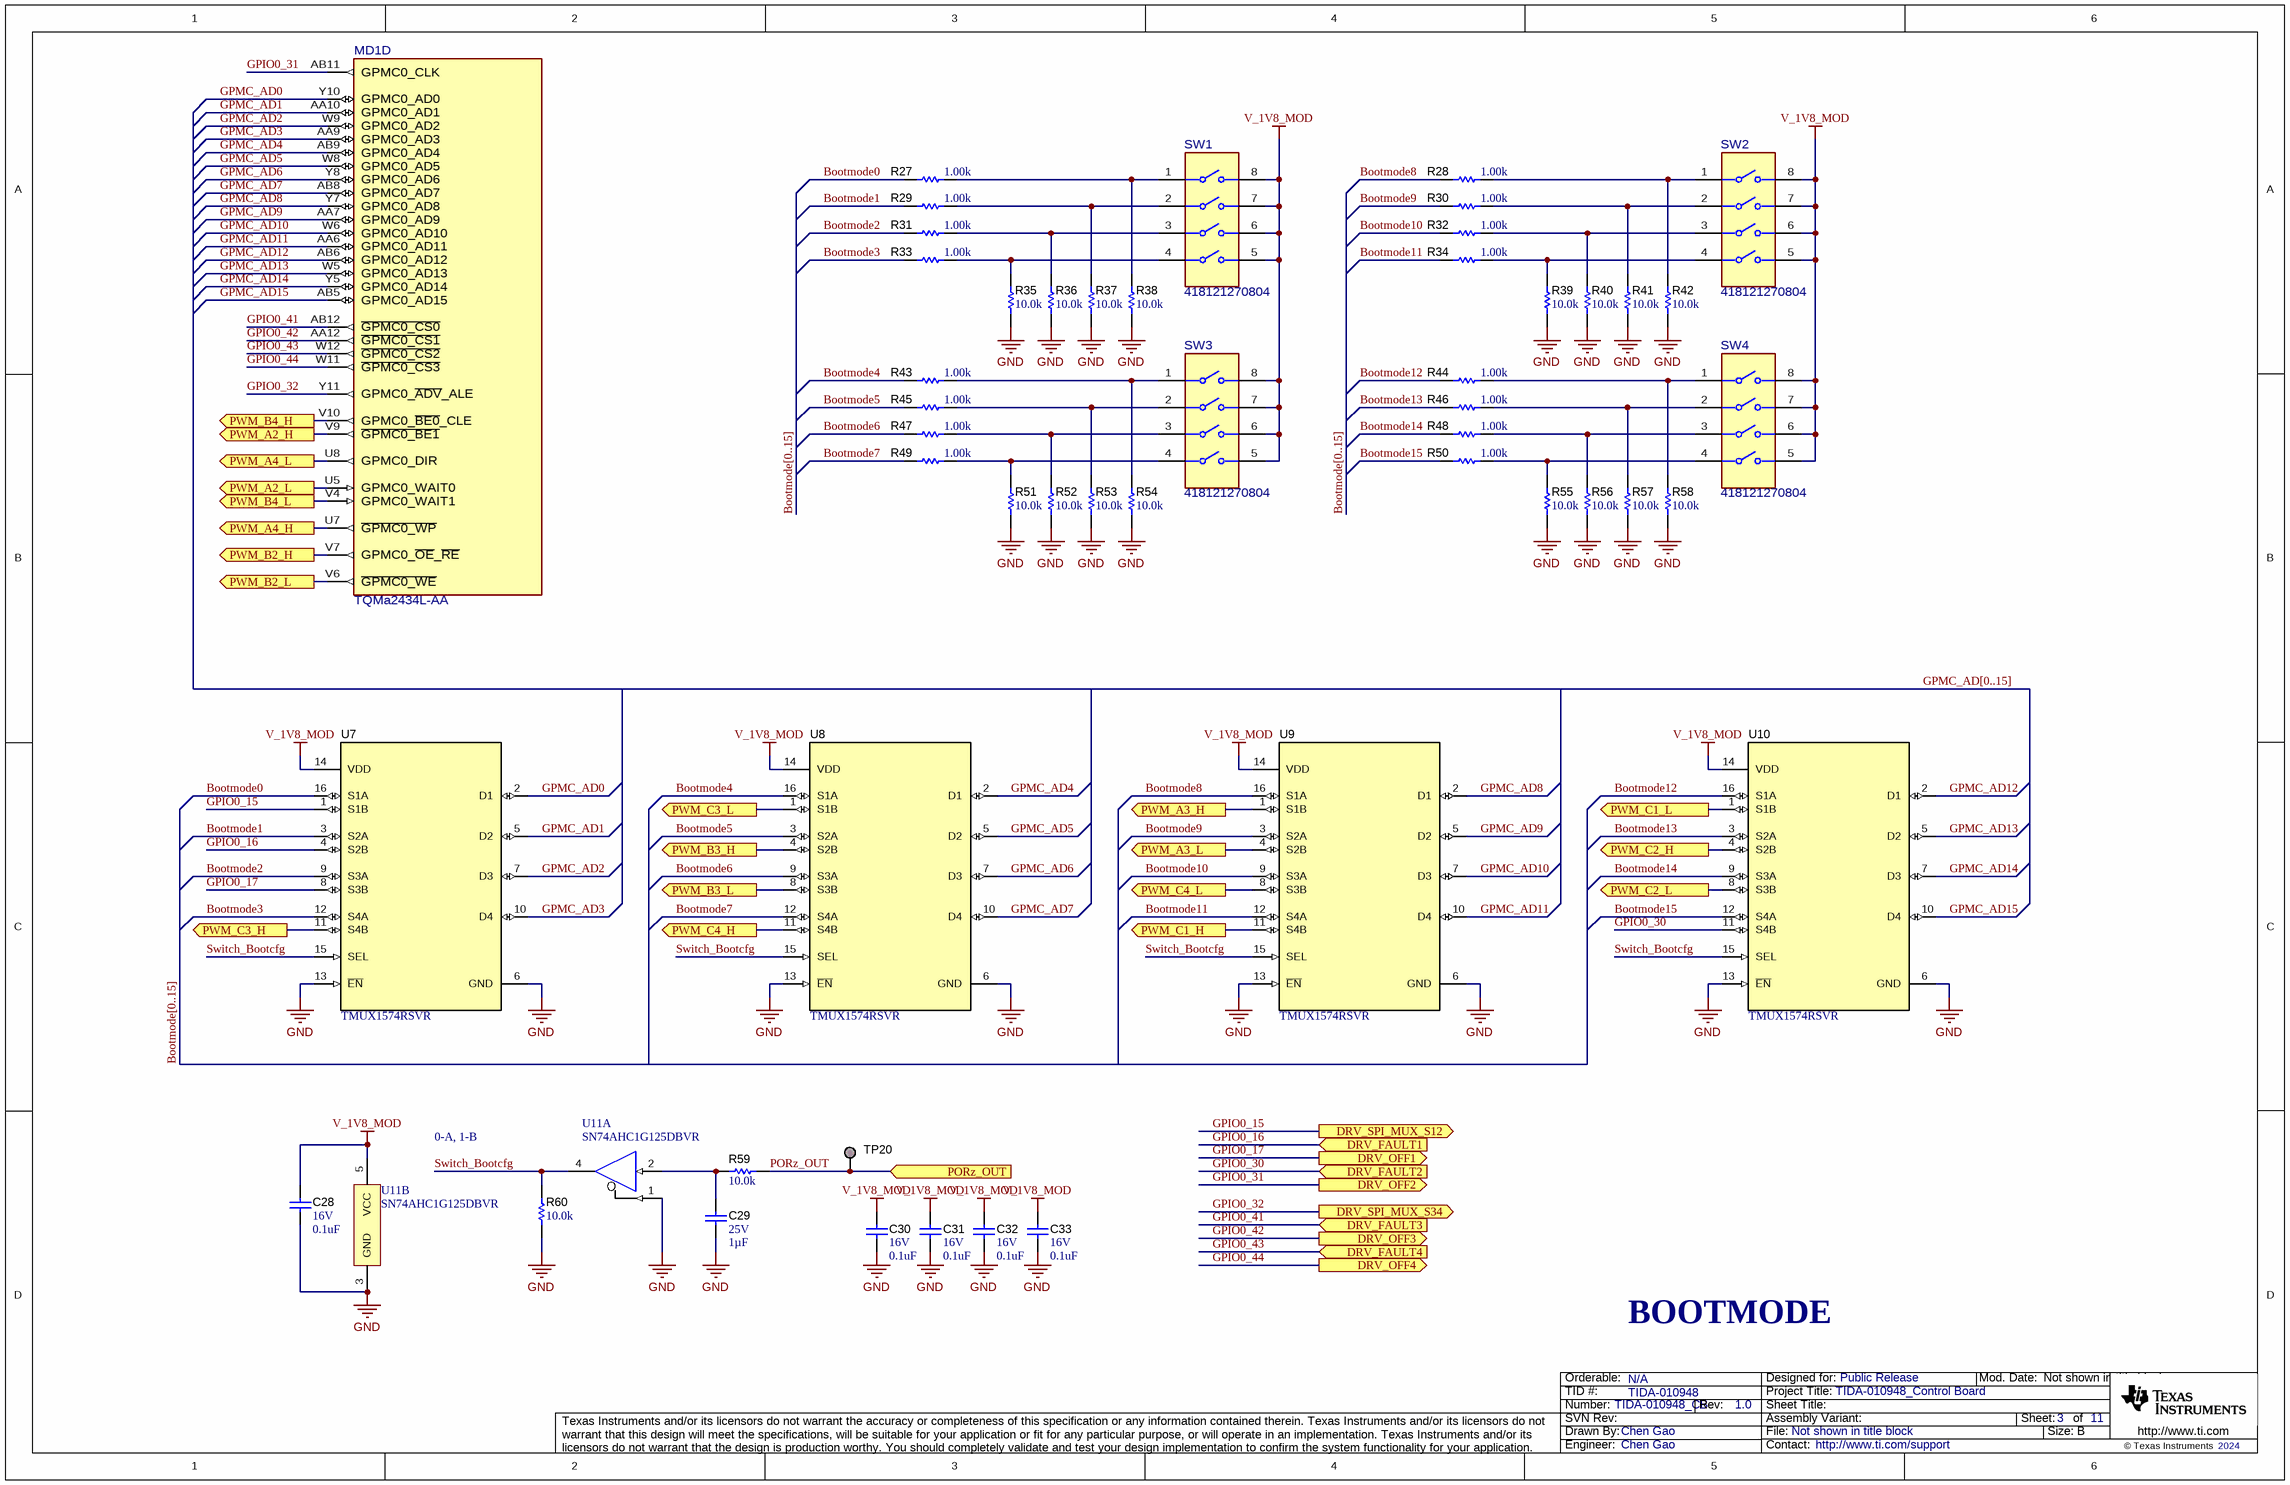
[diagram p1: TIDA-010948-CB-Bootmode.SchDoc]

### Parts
C28  VDC_V: 16V  ValueDisplayed: 0.1uF  [0402L]  (hidden comment: 885012105016)
C29  VDC_V: 25V  ValueDisplayed: 1µF  [0402L]  (hidden comment: GRM155R61E105MA12D)
C30  VDC_V: 16V  ValueDisplayed: 0.1uF  [0402L]  (hidden comment: 885012105016)
C31  VDC_V: 16V  ValueDisplayed: 0.1uF  [0402L]  (hidden comment: 885012105016)
C32  VDC_V: 16V  ValueDisplayed: 0.1uF  [0402L]  (hidden comment: 885012105016)
C33  VDC_V: 16V  ValueDisplayed: 0.1uF  [0402L]  (hidden comment: 885012105016)
MD1  TQMa2434L-AA  [FP-TQMa2434L-AA_LGA366-MFG]  (part D of 9)
R27  ValueDisplayed: 1.00k  [0402L]  (hidden comment: CRCW04021K00FKED)
R28  ValueDisplayed: 1.00k  [0402L]  (hidden comment: CRCW04021K00FKED)
R29  ValueDisplayed: 1.00k  [0402L]  (hidden comment: CRCW04021K00FKED)
R30  ValueDisplayed: 1.00k  [0402L]  (hidden comment: CRCW04021K00FKED)
R31  ValueDisplayed: 1.00k  [0402L]  (hidden comment: CRCW04021K00FKED)
R32  ValueDisplayed: 1.00k  [0402L]  (hidden comment: CRCW04021K00FKED)
R33  ValueDisplayed: 1.00k  [0402L]  (hidden comment: CRCW04021K00FKED)
R34  ValueDisplayed: 1.00k  [0402L]  (hidden comment: CRCW04021K00FKED)
R35  ValueDisplayed: 10.0k  [0402L]  (hidden comment: CRCW040210K0FKED)
R36  ValueDisplayed: 10.0k  [0402L]  (hidden comment: CRCW040210K0FKED)
R37  ValueDisplayed: 10.0k  [0402L]  (hidden comment: CRCW040210K0FKED)
R38  ValueDisplayed: 10.0k  [0402L]  (hidden comment: CRCW040210K0FKED)
R39  ValueDisplayed: 10.0k  [0402L]  (hidden comment: CRCW040210K0FKED)
R40  ValueDisplayed: 10.0k  [0402L]  (hidden comment: CRCW040210K0FKED)
R41  ValueDisplayed: 10.0k  [0402L]  (hidden comment: CRCW040210K0FKED)
R42  ValueDisplayed: 10.0k  [0402L]  (hidden comment: CRCW040210K0FKED)
R43  ValueDisplayed: 1.00k  [0402L]  (hidden comment: CRCW04021K00FKED)
R44  ValueDisplayed: 1.00k  [0402L]  (hidden comment: CRCW04021K00FKED)
R45  ValueDisplayed: 1.00k  [0402L]  (hidden comment: CRCW04021K00FKED)
R46  ValueDisplayed: 1.00k  [0402L]  (hidden comment: CRCW04021K00FKED)
R47  ValueDisplayed: 1.00k  [0402L]  (hidden comment: CRCW04021K00FKED)
R48  ValueDisplayed: 1.00k  [0402L]  (hidden comment: CRCW04021K00FKED)
R49  ValueDisplayed: 1.00k  [0402L]  (hidden comment: CRCW04021K00FKED)
R50  ValueDisplayed: 1.00k  [0402L]  (hidden comment: CRCW04021K00FKED)
R51  ValueDisplayed: 10.0k  [0402L]  (hidden comment: CRCW040210K0FKED)
R52  ValueDisplayed: 10.0k  [0402L]  (hidden comment: CRCW040210K0FKED)
R53  ValueDisplayed: 10.0k  [0402L]  (hidden comment: CRCW040210K0FKED)
R54  ValueDisplayed: 10.0k  [0402L]  (hidden comment: CRCW040210K0FKED)
R55  ValueDisplayed: 10.0k  [0402L]  (hidden comment: CRCW040210K0FKED)
R56  ValueDisplayed: 10.0k  [0402L]  (hidden comment: CRCW040210K0FKED)
R57  ValueDisplayed: 10.0k  [0402L]  (hidden comment: CRCW040210K0FKED)
R58  ValueDisplayed: 10.0k  [0402L]  (hidden comment: CRCW040210K0FKED)
R59  ValueDisplayed: 10.0k  [0402L]  (hidden comment: CRCW040210K0FKED)
R60  ValueDisplayed: 10.0k  [0402L]  (hidden comment: CRCW040210K0FKED)
SW1  418121270804  [FP-418121270804_SMT_SW_11MM1_6MM2-MFG]
SW2  418121270804  [FP-418121270804_SMT_SW_11MM1_6MM2-MFG]
SW3  418121270804  [FP-418121270804_SMT_SW_11MM1_6MM2-MFG]
SW4  418121270804  [FP-418121270804_SMT_SW_11MM1_6MM2-MFG]
TP20  TESTPOINT  [TP_25MIL-SMT]  (value not drawn)  (no BOM)
U7  TMUX1574RSVR  [RSV0016A]
U8  TMUX1574RSVR  [RSV0016A]
U9  TMUX1574RSVR  [RSV0016A]
U10  TMUX1574RSVR  [RSV0016A]
U11  SN74AHC1G125DBVR  [DBV0005A_N]  (parts A,B of 2)

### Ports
DRV_FAULT1 (in), DRV_FAULT2 (in), DRV_FAULT3 (in), DRV_FAULT4 (in), DRV_OFF1 (out), DRV_OFF2 (out), DRV_OFF3 (out), DRV_OFF4 (out), DRV_SPI_MUX_S12 (out), DRV_SPI_MUX_S34 (out), PORz_OUT (in), PWM_A2_H (out), PWM_A2_L (out), PWM_A3_H (out), PWM_A3_L (out), PWM_A4_H (out), PWM_A4_L (out), PWM_B2_H (out), PWM_B2_L (out), PWM_B3_H (out), PWM_B3_L (out), PWM_B4_H (out), PWM_B4_L (out), PWM_C1_H (out), PWM_C1_L (out), PWM_C2_H (out), PWM_C2_L (out), PWM_C3_H (out), PWM_C3_L (out), PWM_C4_H (out), PWM_C4_L (out)

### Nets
GND: C28.2 C29.2 C30.2 C31.2 C32.2 C33.2 R35.1 R36.1 R37.1 R38.1 R39.1 R40.1 R41.1 R42.1 R51.1 R52.1 R53.1 R54.1 R55.1 R56.1 R57.1 R58.1 R60.1 U7.6(GND) U7.13(~{EN}) U8.6(GND) U8.13(~{EN}) U9.6(GND) U9.13(~{EN}) U10.6(GND) U10.13(~{EN}) U11.1(~{OE}) U11.3(GND)
V_1V8_MOD: C28.1 C30.1 C31.1 C32.1 C33.1 SW1.5 SW1.6 SW1.7 SW1.8 SW2.5 SW2.6 SW2.7 SW2.8 SW3.5 SW3.6 SW3.7 SW3.8 SW4.5 SW4.6 SW4.7 SW4.8 U7.14(VDD) U8.14(VDD) U9.14(VDD) U10.14(VDD) U11.5(VCC)
Bootmode0: R27.1 U7.16(S1A)
Bootmode1: R29.1 U7.3(S2A)
Bootmode2: R31.1 U7.9(S3A)
Bootmode3: R33.1 U7.12(S4A)
Bootmode4: R43.1 U8.16(S1A)
Bootmode5: R45.1 U8.3(S2A)
Bootmode6: R47.1 U8.9(S3A)
Bootmode7: R49.1 U8.12(S4A)
Bootmode8: R28.1 U9.16(S1A)
Bootmode9: R30.1 U9.3(S2A)
Bootmode10: R32.1 U9.9(S3A)
Bootmode11: R34.1 U9.12(S4A)
Bootmode12: R44.1 U10.16(S1A)
Bootmode13: R46.1 U10.3(S2A)
Bootmode14: R48.1 U10.9(S3A)
Bootmode15: R50.1 U10.12(S4A)
GPIO0_15: U7.1(S1B) ; port DRV_SPI_MUX_S12
GPIO0_16: U7.4(S2B) ; port DRV_FAULT1
GPIO0_17: U7.8(S3B) ; port DRV_OFF1
GPIO0_30: U10.11(S4B) ; port DRV_FAULT2
GPIO0_31: MD1.AB11(GPMC0_CLK) ; port DRV_OFF2
GPIO0_32: MD1.Y11(GPMC0_~{ADV}_ALE) ; port DRV_SPI_MUX_S34
GPIO0_41: MD1.AB12(~{GPMC0_CS0}) ; port DRV_FAULT3
GPIO0_42: MD1.AA12(~{GPMC0_CS1}) ; port DRV_OFF3
GPIO0_43: MD1.W12(~{GPMC0_CS2}) ; port DRV_FAULT4
GPIO0_44: MD1.W11(~{GPMC0_CS3}) ; port DRV_OFF4
GPMC_AD0: MD1.Y10(GPMC0_AD0) U7.2(D1)
GPMC_AD1: MD1.AA10(GPMC0_AD1) U7.5(D2)
GPMC_AD2: MD1.W9(GPMC0_AD2) U7.7(D3)
GPMC_AD3: MD1.AA9(GPMC0_AD3) U7.10(D4)
GPMC_AD4: MD1.AB9(GPMC0_AD4) U8.2(D1)
GPMC_AD5: MD1.W8(GPMC0_AD5) U8.5(D2)
GPMC_AD6: MD1.Y8(GPMC0_AD6) U8.7(D3)
GPMC_AD7: MD1.AB8(GPMC0_AD7) U8.10(D4)
GPMC_AD8: MD1.Y7(GPMC0_AD8) U9.2(D1)
GPMC_AD9: MD1.AA7(GPMC0_AD9) U9.5(D2)
GPMC_AD10: MD1.W6(GPMC0_AD10) U9.7(D3)
GPMC_AD11: MD1.AA6(GPMC0_AD11) U9.10(D4)
GPMC_AD12: MD1.AB6(GPMC0_AD12) U10.2(D1)
GPMC_AD13: MD1.W5(GPMC0_AD13) U10.5(D2)
GPMC_AD14: MD1.Y5(GPMC0_AD14) U10.7(D3)
GPMC_AD15: MD1.AB5(GPMC0_AD15) U10.10(D4)
PORz_OUT: R59.1 TP20.1 ; port PORz_OUT
PWM_A2_H: MD1.V9(~{GPMC0_BE1}) ; port PWM_A2_H
PWM_A2_L: MD1.U5(GPMC0_WAIT0) ; port PWM_A2_L
PWM_A3_H: U9.1(S1B) ; port PWM_A3_H
PWM_A3_L: U9.4(S2B) ; port PWM_A3_L
PWM_A4_H: MD1.U7(~{GPMC0_WP}) ; port PWM_A4_H
PWM_A4_L: MD1.U8(GPMC0_DIR) ; port PWM_A4_L
PWM_B2_H: MD1.V7(GPMC0_~{OE}_~{RE}) ; port PWM_B2_H
PWM_B2_L: MD1.V6(~{GPMC0_WE}) ; port PWM_B2_L
PWM_B3_H: U8.4(S2B) ; port PWM_B3_H
PWM_B3_L: U8.8(S3B) ; port PWM_B3_L
PWM_B4_H: MD1.V10(GPMC0_~{BE0}_CLE) ; port PWM_B4_H
PWM_B4_L: MD1.V4(GPMC0_WAIT1) ; port PWM_B4_L
PWM_C1_H: U9.11(S4B) ; port PWM_C1_H
PWM_C1_L: U10.1(S1B) ; port PWM_C1_L
PWM_C2_H: U10.4(S2B) ; port PWM_C2_H
PWM_C2_L: U10.8(S3B) ; port PWM_C2_L
PWM_C3_H: U7.11(S4B) ; port PWM_C3_H
PWM_C3_L: U8.1(S1B) ; port PWM_C3_L
PWM_C4_H: U8.11(S4B) ; port PWM_C4_H
PWM_C4_L: U9.8(S3B) ; port PWM_C4_L
Switch_Bootcfg: R60.2 U7.15(SEL) U8.15(SEL) U9.15(SEL) U10.15(SEL) U11.4(Y)
NetC29_1: C29.1 R59.2 U11.2(A)
NetR27_2: R27.2 R38.2 SW1.1
NetR28_2: R28.2 R42.2 SW2.1
NetR29_2: R29.2 R37.2 SW1.2
NetR30_2: R30.2 R41.2 SW2.2
NetR31_2: R31.2 R36.2 SW1.3
NetR32_2: R32.2 R40.2 SW2.3
NetR33_2: R33.2 R35.2 SW1.4
NetR34_2: R34.2 R39.2 SW2.4
NetR43_2: R43.2 R54.2 SW3.1
NetR44_2: R44.2 R58.2 SW4.1
NetR45_2: R45.2 R53.2 SW3.2
NetR46_2: R46.2 R57.2 SW4.2
NetR47_2: R47.2 R52.2 SW3.3
NetR48_2: R48.2 R56.2 SW4.3
NetR49_2: R49.2 R51.2 SW3.4
NetR50_2: R50.2 R55.2 SW4.4

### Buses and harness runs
bus Bootmode[0..15]
bus GPMC_AD[0..15]

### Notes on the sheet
- 0-A, 1-B
- BOOTMODE

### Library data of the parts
C28 C30-C33 = CMP-0006223-2: CAP, CERM, 0.1 uF, 16 V, +/- 20%, X5R, 0402; Manufacturer: Wurth Elektronik; TaMin_C: -55°C; Polarized: N; SizeAreaWB_mm2: 3; Value1: Unknown; U/M: EA; Value: 0.1uF; TaMax_C: 85°C; SizeZ_mm: 0.6; SizeX_mm: 1; SizeY_mm: 0.5; Cap_Case: 0402; Cap_F: 100nF; AEC Category: Q200
C29 = CMP-0078625-1: CAP, CERM, 1 µF, 25 V,+/- 20%, X5R, 0402; Manufacturer: MuRata; SizeAreaWB_mm2: 3; SizeArea_mm2: 0.5; AEC Qualified: N; AEC Category: Q200; Value: 1uF; TaMax_C: 85°C; SizeZ_mm: 0.6; TaMin_C: -55°C; U/M: EA; SizeX_mm: 1; Cap_Case: 0402
MD1 = CMP-0120622-1: as MD1 on sheet TIDA-010948-CB-Power
R27-R34 R43-R50 = CMP-0026071-3: RES, 1.00 k, 1%, 0.063 W, AEC-Q200 Grade 0, 0402; Manufacturer: Vishay-Dale; Power_W: 63mW; TempCo: 100 ppm/C; Value_Code: 1k00; Value: 1.00k; EIA_Code: E96; Res_ohm: 1k; SizeX_mm: 1; SizeY_mm: 0.5; SizeZ_mm: 0.6; Value2: 0.063W; AEC Qualified: Y; VDC_V: 50V; AEC Category: Q200; AEC Grade: 0
R35-R42 R51-R60 = CMP-0025958-3: as R6 on sheet TIDA-010948-CB-Power
SW1-SW4 = CMP-0096367-1: Dip Switch SPST 4 Position Surface Mount Slide (Standard) Actuator 25mA 24VDC; Manufacturer: Wurth Electronics; AEC Qualified: No; VDC_V: 24V; Coil Resistance_ohm: 50mΩ; Circuit: SPST-NO; Electromechanical Life: 2000Cycles; SizeZ_mm: 4.62mm; Standoff Height: 0.6mm; PositionCount: 4
TP20 = CMP-0078143-3: TEST POINT.  No entry in BOM.
U7-U10 = CMP-0086167-2: Low-capacitance, 2:1 (SPDT) 4-channel, powered-off protection switch with 1.8 V logic, RSV0016A (UQFN-16); Manufacturer: Texas Instruments; SizeArea_mm2: 4.68; AEC Category: Q200; Rating: Catalog; SizeAreaWB_mm2: 10.08; SizeX_mm: 1.8; SizeY_mm: 2.6; SizeZ_mm: 0.55; CompType: IC; AEC Qualified: N
U11 = CMP-0051315-2: Single Bus Buffer Gate with 3-State Output, DBV0005A (SOT-23-5); Manufacturer: Texas Instruments; Schmitt Trigger: No; F @ Nom Voltage(Max)(Mhz): 75; VCC(Max)(V): 5.5; Input Type: CMOS; Rating: Catalog; VCC(Min)(V): 2; 3-State Output: Yes; ICC @ Nom Voltage(Max)(mA): 0.01; Output Drive (IOL/IOH)(Max)(mA): 50/-50; Voltage(Nom)(V): 3.3,5; Bits(#): 1; Logic: True; tpd @ Nom Voltage(Max)(ns): 11.5,7.5; AEC Category: Q200; AEC Qualified: N; CompType: IC; SizeAreaWB_mm2: 14.82; SizeArea_mm2: 8.12; SizeX_mm: 2.8; SizeY_mm: 2.9; SizeZ_mm: 1.45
